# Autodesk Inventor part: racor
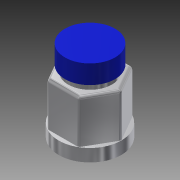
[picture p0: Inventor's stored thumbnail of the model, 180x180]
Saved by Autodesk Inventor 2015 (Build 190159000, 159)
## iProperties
Created: 2016-06
Part Number: racor
Material: Genérico
Document SubType Name: Modeling
Designer: Diego
Density: 1 g/cm^3
Appearance: Valor por defecto
Author: Diego
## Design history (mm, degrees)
sketch "Boceto1"
  geometry: C1 r 5 at (0, 0); 1 further point
  constraints: 1 centre point, 1 coincident
  dimensions: "d0" = 10 diameter of C1
extrude "Extrusión1" new body sketch "Boceto1" distance "d1" = 2; taper "d2" = 0 deg
sketch "Boceto2"
  geometry: L1 (-5, 0.009)-(-2.492, 4.335); L2 (-2.492, 4.335)-(2.508, 4.326); L3 (2.508, 4.326)-(5, 0.009); L4 (5, 0.009)-(2.508, -4.326); L5 (2.508, -4.326)-(-2.492, -4.335); L6 (-2.492, -4.335)-(-5, 0.009); A1 r 5 centre (0, 0) between (-5, 0.009) and (-2.492, 4.335) reference; 2 further points
  constraints: 12 end point, 6 point on circle, 2 other
  dimensions: "d3" = 5 distance of L1.start L1.end; "d4" = 5 distance of L1.end L2.end; "d5" = 4.98452 distance of L2.end L3.end; "d6" = 5 distance of L3.end L4.end; "d7" = 5 distance of L4.end L5.end
extrude "Extrusión2" join sketch "Boceto2" distance "d8" = 7; taper "d9" = 0 deg
sketch "Boceto3"
  geometry: C1 r 3.5 at (0, 0); 1 further point
  constraints: 1 centre point, 1 coincident
  dimensions: "d10" = 7 diameter of C1
extrude "Extrusión3" join sketch "Boceto3" distance "d11" = 1; taper "d12" = 0 deg
sketch "Boceto4"
  geometry: C1 r 4 at (0, 0); 1 further point
  constraints: 1 centre point, 1 coincident
  dimensions: "d13" = 8 diameter of C1
extrude "Extrusión4" join sketch "Boceto4" distance "d14" = 3; taper "d15" = 0 deg
fillet "Empalme1" dims "d16" = 0.5
node "Sólido1"
